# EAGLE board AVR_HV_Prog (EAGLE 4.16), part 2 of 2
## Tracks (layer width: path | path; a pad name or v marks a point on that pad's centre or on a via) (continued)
PAGEL  (via drill 0.5 pad 1.27, 0.6 pad 1.27) (continued)
  Top 0.406: 56.2,57.17 55.79,58.27 | 55.79,58.27 v56.2,58.42 | 56.2,57.17 56.6,58.27 | v56.2,58.42 56.6,58.27 | 56.2,57.17 55.79,58.27 | v56.2,58.42 55.79,58.27 | 55.78,40.13 56.2,41.51 | 55.78,40.13 | 56.2,41.51 | 55.78,40.13 56.2,41.51 | 55.78,40.13 | v56.2,40.01 55.78,40.13 | 56.61,40.13 56.2,41.51 | 55.78,40.13 56.2,41.51 | v56.2,40.01 55.78,40.13 | 56.61,40.13 56.2,41.51 | 56.61,40.13 | v56.2,40.01 56.61,40.13 | 55.78,40.13 56.2,41.51 | v56.2,40.01 55.78,40.13 | 56.61,40.13 56.2,41.51 | v56.2,40.01 56.61,40.13
  Top 0.61: 56.2,59.67 | 56.2,59.67 56.2,69.87 | 56.2,69.87 | 56.2,41.51 | 56.2,41.51 56.2,57.17 | 56.2,57.17
  Bottom 0.61: IC6.2 79.38,57.15 78.11,58.42 57.45,58.42 | v56.2,71.12 54.95,71.12 | 54.95,71.12 IC4.13 | v56.2,58.42 57.45,58.42 | 46.35,30.16 46.35,28.89 45.4,27.94 45.4,24.77 46.04,24.13 47.62,24.13 49.53,22.23 IC3.17 49.53,20.95 50.48,20 50.48,14.29 49.85,13.65 48.26,13.65 46.99,12.38 IC2.21 | 46.35,30.16 46.99,30.8 50.8,30.8 52.7,32.7 53.34,32.7 56.2,35.56 56.2,38.51 | 56.2,38.51 v56.2,40.01 | R18.2 40.96,30.8 45.72,30.8 46.35,30.16 | 54.95,71.12 56.11,70.8 v56.2,71.12 | 54.95,71.12 56.11,71.44 v56.2,71.12 | 57.45,58.42 56.28,58.74 v56.2,58.42 | 57.45,58.42 56.28,58.1 v56.2,58.42 | 56.2,38.51 56.52,39.93 v56.2,40.01 | 56.2,38.51 55.88,39.93 v56.2,40.01
R/B  (via drill 0.5 pad 1.27, 0.6 pad 1.27)
  Top 0.406: v68.9,52.39 68.9,53.64 | 68.9,59.71 v68.9,60.96 | v70.17,44.77 71.67,44.77 | 74.7,44.77 v76.2,44.77 | 49.76,15.56 v48.26,15.56 | v58.42,15.56 56.92,15.56 | 68.9,59.71 69.34,60.77 v68.9,60.96 | 68.9,59.71 68.45,60.77 v68.9,60.96 | 68.9,59.71 69.34,60.77 | 68.9,59.71 68.45,60.77 | 68.9,59.71 69.34,60.77 | v68.9,60.96 69.34,60.77 | 68.9,59.71 68.45,60.77 | v68.9,60.96 68.45,60.77 | 68.9,53.64 68.45,52.57 | v68.9,52.39 68.45,52.57 | 68.9,53.64 69.34,52.57 | v68.9,52.39 69.34,52.57 | 68.45,52.57 68.9,53.64 | 69.34,52.57 68.9,53.64 | 68.9,53.64 68.45,52.57 | v68.9,52.39 68.45,52.57 | 68.9,53.64 69.34,52.57 | v68.9,52.39 69.34,52.57 | 74.7,44.77 76.05,44.31 | v76.2,44.77 76.05,44.31 | 74.7,44.77 76.05,45.22 | v76.2,44.77 76.05,45.22 | 74.7,44.77 76.05,44.31 | 74.7,44.77 76.05,45.22 | 74.7,44.77 76.05,44.31 | v76.2,44.77 76.05,44.31 | 74.7,44.77 76.05,45.22 | v76.2,44.77 76.05,45.22 | 71.67,44.77 70.32,45.22 | v70.17,44.77 70.32,45.22 | 71.67,44.77 70.32,44.31 | v70.17,44.77 70.32,44.31 | 71.67,44.77 70.32,45.22 | 71.67,44.77 70.32,44.31 | 70.32,45.22 71.67,44.77 | v70.17,44.77 70.32,45.22 | 70.32,44.31 71.67,44.77 | v70.17,44.77 70.32,44.31 | 49.76,15.56 48.41,16.01 | v48.26,15.56 48.41,16.01 | 49.76,15.56 48.41,15.1 | v48.26,15.56 48.41,15.1 | 49.76,15.56 48.41,16.01 | 49.76,15.56 48.41,15.1 | 49.76,15.56 48.41,16.01 | v48.26,15.56 48.41,16.01 | 49.76,15.56 48.41,15.1 | v48.26,15.56 48.41,15.1 | 56.92,15.56 58.27,15.1 | v58.42,15.56 58.27,15.1 | 56.92,15.56 58.27,16.01 | v58.42,15.56 58.27,16.01 | 58.27,15.1 56.92,15.56 | 58.27,16.01 56.92,15.56 | 56.92,15.56 58.27,15.1 | v58.42,15.56 58.27,15.1 | 56.92,15.56 58.27,16.01 | v58.42,15.56 58.27,16.01 | 69.3,60.81 68.9,59.71
  Top 0.406: 68.9,59.71 | 68.49,60.81 68.9,59.71 | 68.9,59.71 69.3,60.81 | 69.3,60.81 v68.9,60.96 | 68.9,59.71 68.49,60.81 | 68.49,60.81 v68.9,60.96 | 68.9,59.71 69.3,60.81 | v68.9,60.96 69.3,60.81 | 68.9,59.71 68.49,60.81 | v68.9,60.96 68.49,60.81 | 68.9,53.64 | 68.49,52.54 68.9,53.64 | 68.49,52.54 | v68.9,52.39 68.49,52.54 | 69.3,52.54 68.9,53.64 | 69.3,52.54 | v68.9,52.39 69.3,52.54 | 68.49,52.54 68.9,53.64 | 69.3,52.54 68.9,53.64 | 68.49,52.54 68.9,53.64 | v68.9,52.39 68.49,52.54 | 69.3,52.54 68.9,53.64 | v68.9,52.39 69.3,52.54 | 76.08,44.35 74.7,44.77 | 76.08,44.35 | 74.7,44.77 | 74.7,44.77 76.08,44.35 | 76.08,44.35 | v76.2,44.77 76.08,44.35 | 76.08,45.18 74.7,44.77 | 74.7,44.77 76.08,44.35 | 76.08,44.35 v76.2,44.77 | 74.7,44.77 76.08,45.18 | 76.08,45.18 | 76.08,45.18 v76.2,44.77 | 74.7,44.77 76.08,44.35 | v76.2,44.77 76.08,44.35 | 76.08,45.18 74.7,44.77 | 76.08,45.18 v76.2,44.77 | 70.29,45.18 71.67,44.77 | 70.29,45.18 | 70.29,45.18 71.67,44.77 | v70.17,44.77 70.29,45.18 | 71.67,44.77 | 70.29,44.35 71.67,44.77 | 70.29,44.35 | v70.17,44.77 70.29,44.35 | 70.29,45.18 71.67,44.77 | 70.29,44.35 71.67,44.77 | v70.17,44.77 70.29,44.35 | 70.29,45.18 71.67,44.77 | v70.17,44.77 70.29,45.18 | 70.29,44.35 71.67,44.77 | v70.17,44.77 70.29,44.35 | 49.76,15.56 48.38,15.97 | 48.38,15.97 | 48.38,15.97 49.76,15.56 | 48.38,15.97 v48.26,15.56 | 49.76,15.56 | 48.38,15.14 49.76,15.56 | 48.38,15.14 | 48.38,15.14 v48.26,15.56 | 49.76,15.56 48.38,15.97 | 49.76,15.56 48.38,15.14 | 48.38,15.14 v48.26,15.56 | 48.38,15.97 49.76,15.56 | 48.38,15.97 v48.26,15.56 | 49.76,15.56 48.38,15.14 | v48.26,15.56 48.38,15.14 | 58.3,15.14 56.92,15.56 | 58.3,15.14 | 56.92,15.56 | 58.3,15.14 56.92,15.56 | 58.3,15.14 | v58.42,15.56 58.3,15.14 | 58.3,15.97 56.92,15.56
  Top 0.406: 58.3,15.14 56.92,15.56 | v58.42,15.56 58.3,15.14 | 58.3,15.97 56.92,15.56 | 58.3,15.97 v58.42,15.56 | 58.3,15.14 56.92,15.56 | v58.42,15.56 58.3,15.14 | 58.3,15.97 56.92,15.56 | v58.42,15.56 58.3,15.97
  Top 0.61: 68.9,53.64 | 68.9,53.64 68.9,59.71 | 68.9,59.71 | 71.67,44.77 | 71.67,44.77 74.7,44.77 | 74.7,44.77 | 56.92,15.56 | 56.92,15.56 49.76,15.56 | 49.76,15.56
  Bottom 0.61: IC6.3 79.38,59.69 78.11,60.96 70.15,60.96 | v76.2,44.77 76.2,43.27 | 76.2,43.27 IC5.9 | v68.9,60.96 70.15,60.96 | v70.17,44.77 70.8,44.77 71.44,45.4 71.44,45.57 | v70.17,44.77 68.67,44.77 | 68.67,44.77 67.63,44.77 66.67,43.81 66.67,42.23 65.41,40.96 65.41,35.24 59.69,29.53 IC2.15 59.69,26.35 61.91,24.13 62.87,24.13 64.77,22.23 IC3.11 64.77,20.64 62.23,18.1 62.23,14.92 | 68.01,51.5 62.23,45.72 IC4.3 51.44,45.72 49.85,44.13 49.85,39.05 50.8,38.1 50.8,33.97 49.53,32.7 33.02,32.7 | 68.01,51.5 v68.9,52.39 | 71.44,45.57 71.44,47.62 73.34,49.53 73.34,51.12 72.07,52.39 70.15,52.39 | v68.9,52.39 70.15,52.39 | 33.02,32.7 27.3,32.7 26.99,32.38 17.14,32.38 R13.2 | 33.02,32.7 JP1.1 | 62.23,14.92 63.5,13.65 IC7.9 | IC8.7 40.64,15.88 42.23,14.29 46.35,14.29 46.99,14.92 47.08,14.92 | v48.26,15.56 47.08,14.92 | v58.42,15.56 58.42,15.24 59.31,14.67 | 59.31,14.67 59.69,14.29 61.59,14.29 62.23,14.92 | 70.15,60.96 68.98,61.28 v68.9,60.96 | 70.15,60.96 68.98,60.64 v68.9,60.96 | 68.01,51.5 69.06,52.1 v68.9,52.39 | 68.01,51.5 68.61,52.55 v68.9,52.39 | 70.15,52.39 68.98,52.71 v68.9,52.39 | 70.15,52.39 68.98,52.07 v68.9,52.39 | 76.2,43.27 76.52,44.7 v76.2,44.77 | 76.2,43.27 75.88,44.7 v76.2,44.77 | 68.67,44.77 70.09,44.45 v70.17,44.77 | 68.67,44.77 70.09,45.09 v70.17,44.77 | 71.44,45.57 70.06,45.08 v70.17,44.77 | 71.44,45.57 70.4,44.53 v70.17,44.77 | 47.08,14.92 48.19,15.23 v48.26,15.56 | 47.08,14.92 48.19,15.88 v48.26,15.56 | 59.31,14.67 58.72,15.69 v58.42,15.56 | 59.31,14.67 58.2,15.31 v58.42,15.56
U_IN
  Bottom 0.61: X2.+ 8.26,13.97 8.26,12.38 9.21,11.43 IC10.IN 13.02,5.71 13.84,4.89 C4.+
VCC  (via drill 0.6 pad 1.27)
  Top 0.406: v31.75,54.61 31.75,56.11 | 31.75,72.16 31.74,72.19 | 31.74,72.19 v31.43,73.66 | v18.1,26.04 17.78,27.54 | 17.78,42.95 v17.78,44.45 | 31.75,72.16 31.89,73.5 v31.43,73.66 | 31.73,72.19 30.98,73.5 | 30.98,73.5 v31.43,73.66 | 31.75,72.16 31.75,72.19 | 31.75,72.16 31.73,72.19 | 31.75,72.19 31.89,73.19 v31.43,73.66 | 31.75,72.19 31.75,72.16 | 31.73,72.19 30.98,73.5 | 31.73,72.19 | 31.73,72.19 31.75,72.16 | 30.98,73.5 v31.43,73.66 | 31.75,56.11 31.29,54.77 | v31.75,54.61 31.29,54.77 | 31.75,56.11 32.21,54.77 | v31.75,54.61 32.21,54.77 | 31.29,54.77 31.75,56.11 | 32.21,54.77 31.75,56.11 | 31.75,56.11 31.29,54.77 | v31.75,54.61 31.29,54.77 | 31.75,56.11 32.21,54.77 | v31.75,54.61 32.21,54.77 | 17.78,42.95 18.24,44.3 | v17.78,44.45 18.24,44.3 | 17.78,42.95 17.32,44.3 | v17.78,44.45 17.32,44.3 | 17.78,42.95 18.24,44.3 | 17.78,42.95 17.32,44.3 | 17.78,42.95 18.24,44.3 | v17.78,44.45 18.24,44.3 | 17.78,42.95 17.32,44.3 | v17.78,44.45 17.32,44.3 | 17.64,26.19 17.78,27.5 | v18.1,26.04 17.64,26.19 | 17.78,28.89 17.78,33.02 | 17.78,39.69 17.78,42.95 | 17.78,42.95 | 18.55,26.19 17.8,27.5 | v18.1,26.04 18.55,26.19 | 17.64,26.19 17.78,27.5 | 17.78,27.5 17.78,27.54 | 17.8,27.5 17.78,27.54 | 17.78,27.54 17.78,27.5 | 17.64,26.19 17.78,27.5 | v18.1,26.04 17.64,26.19 | 17.78,27.54 17.8,27.5 | 18.55,26.19 17.8,27.5 | v18.1,26.04 18.55,26.19 | 31.74,72.19 31.86,73.62 | 31.86,73.62 v31.43,73.66 | 31.74,72.19 31.05,73.45 | 31.05,73.45 v31.43,73.66 | 31.86,73.62 31.75,72.19 31.05,73.45 | 31.86,73.63 31.86,73.62 | v31.43,73.66 31.86,73.63 | v31.43,73.66 31.05,73.45 | 31.75,72.19 31.86,73.62 | 31.86,73.62 31.86,73.63 | 31.75,72.19 31.05,73.45 | 31.73,72.19 31.86,73.62 | 31.86,73.62 | v31.43,73.66 31.86,73.62
  Top 0.406: 31.73,72.19 31.05,73.45 | 31.05,73.45 | 31.86,73.62 31.75,72.19 | 31.86,73.62 31.86,73.63 | v31.43,73.66 31.86,73.63 | 31.05,73.45 31.75,72.19 | 31.05,73.45 v31.43,73.66 | 31.73,72.19 31.86,73.62 | 31.86,73.62 v31.43,73.66 | 31.73,72.19 31.05,73.45 | v31.43,73.66 31.05,73.45 | 31.34,54.73 31.75,56.11 | 31.34,54.73 | 31.34,54.73 | v31.75,54.61 31.34,54.73 | 31.34,54.73 31.75,56.11 | v31.75,54.61 31.34,54.73 | 32.16,54.73 31.75,56.11 | 32.16,54.73 | v31.75,54.61 32.16,54.73 | 31.34,54.73 31.75,56.11 | v31.75,54.61 31.34,54.73 | 31.75,56.11 | 32.16,54.73 31.75,56.11 | v31.75,54.61 32.16,54.73 | 17.78,42.95 18.19,44.33 | 18.19,44.33 | 18.19,44.33 17.78,42.95 | 18.19,44.33 v17.78,44.45 | 17.78,42.95 | 17.37,44.33 17.78,42.95 | 17.37,44.33 | 17.37,44.33 v17.78,44.45 | 17.78,42.95 18.19,44.33 | 17.78,42.95 17.37,44.33 | 17.37,44.33 v17.78,44.45 | 18.19,44.33 17.78,42.95 | 18.19,44.33 v17.78,44.45 | 17.78,42.95 17.37,44.33 | v17.78,44.45 17.37,44.33 | 17.67,26.07 17.79,27.5 18.48,26.25 | 17.67,26.07 v18.1,26.04 | 18.48,26.25 18.48,26.24 v18.1,26.04 | 18.48,26.25 | 18.48,26.25 17.8,27.5 | 18.48,26.25 18.48,26.24 | 17.67,26.07 17.78,27.5 | 18.48,26.25 17.78,27.5 | v18.1,26.04 18.48,26.25 | 17.67,26.07 17.8,27.5 | 18.48,26.24 17.8,27.5 | 17.67,26.07 17.78,27.5 | 17.67,26.07 v18.1,26.04 | 18.48,26.25 17.78,27.5 | v18.1,26.04 18.48,26.25 | 17.67,26.07 17.8,27.5 | v18.1,26.04 17.67,26.07 | 18.48,26.24 17.8,27.5 | v18.1,26.04 18.48,26.24
  Top 0.61: 31.75,56.11 | 31.75,56.11 31.75,72.16 | 17.78,27.54 17.78,28.89 | 17.78,33.02 17.78,39.69
  Bottom 0.61: Q5.1 R10.2 31.96,53.12 | IC11.6 20.95,17.78 19.68,19.05 R14.1 18.1,19.05 15.43,21.72 15.43,21.78 | v31.43,73.66 29.93,73.66 | 29.93,73.66 IC1.9 | v31.75,54.61 31.75,53.34 | 31.75,53.34 31.96,53.12 | 31.43,56.11 31.43,56.52 30.8,57.15 26.67,57.15 22.86,53.34 IC1.20 C5.1 18.1,46.67 18.1,45.92 | 31.43,56.11 v31.75,54.61 | 31.75,53.34 30.95,53.34 | 30.95,53.34 IC1.1 | 15.43,21.78 C2.+ 15.43,24.64 16.19,25.4 16.74,25.4 | 15.43,21.78 13.02,19.37 IC10.OUT | 18.1,45.92 18.1,44.77 v17.78,44.45 | 16.74,25.4 17.46,25.4 v18.1,26.04 | 29.93,73.66 31.36,73.34 v31.43,73.66 | 29.93,73.66 31.36,73.98 v31.43,73.66 | 31.96,53.12 32.08,54.58 v31.75,54.61 | 31.96,53.12 31.44,54.49 v31.75,54.61 | 31.43,56.11 31.43,54.68 v31.75,54.61 | 31.43,56.11 32.07,54.68 v31.75,54.61 | 30.95,53.34 31.98,54.38 v31.75,54.61 | 30.95,53.34 31.44,54.72 v31.75,54.61 | 18.1,45.92 17.48,44.59 v17.78,44.45 | 18.1,45.92 18.11,44.45 v17.78,44.45 | 16.74,25.4 18.17,25.71 v18.1,26.04 | 16.74,25.4 17.89,26.3 v18.1,26.04
VCC_P  (via drill 0.6 pad 1.27)
  Top 0.406: v70.48,30.48 71.98,30.48 | 82.32,30.48 v83.82,30.48 | v41.91,59.69 41.91,61.19 | 41.91,74.7 v41.91,76.2 | v41.91,49.53 41.91,51.03 | 41.91,58.19 v41.91,59.69 | v40.64,13.65 42.14,13.65 | 64.22,13.65 64.54,13.65 | 64.54,13.65 v66.04,13.65 | 82.32,30.48 83.67,30.02 | v83.82,30.48 83.67,30.02 | 82.32,30.48 83.67,30.94 | v83.82,30.48 83.67,30.94 | 82.32,30.48 83.67,30.02 | 82.32,30.48 83.67,30.94 | 82.32,30.48 83.67,30.02 | v83.82,30.48 83.67,30.02 | 82.32,30.48 83.67,30.94 | v83.82,30.48 83.67,30.94 | 71.98,30.48 70.64,30.94 | v70.48,30.48 70.64,30.94 | 71.98,30.48 | 82.32,30.48 | 71.98,30.48 70.64,30.02 | v70.48,30.48 70.64,30.02 | 71.98,30.48 70.64,30.94 | 71.98,30.48 70.64,30.02 | 70.64,30.94 71.98,30.48 | v70.48,30.48 70.64,30.94 | 70.64,30.02 71.98,30.48 | v70.48,30.48 70.64,30.02 | 41.91,74.7 42.37,76.05 | v41.91,76.2 42.37,76.05 | 41.91,74.7 41.45,76.05 | v41.91,76.2 41.45,76.05 | 41.91,74.7 42.37,76.05 | 41.91,74.7 41.45,76.05 | 41.91,74.7 42.37,76.05 | v41.91,76.2 42.37,76.05 | 41.91,74.7 41.45,76.05 | v41.91,76.2 41.45,76.05 | 41.91,61.19 41.45,59.84 | v41.91,59.69 41.45,59.84 | 41.91,61.19 42.37,59.84 | v41.91,59.69 42.37,59.84 | 41.91,58.19 42.37,59.53 | v41.91,59.69 42.37,59.53 | 41.91,58.19 41.45,59.53 | v41.91,59.69 41.45,59.53 | 41.45,59.84 41.91,61.19 | 42.37,59.84 41.91,61.19 | 41.91,61.19 41.45,59.84 | v41.91,59.69 41.45,59.84 | 41.91,61.19 42.37,59.84 | v41.91,59.69 42.37,59.84 | 41.91,58.19 42.37,59.53 | 41.91,58.19 41.45,59.53 | 41.91,58.19 42.37,59.53 | v41.91,59.69 42.37,59.53 | 41.91,58.19 41.45,59.53 | v41.91,59.69 41.45,59.53 | 41.91,51.03 41.45,49.69 | v41.91,49.53 41.45,49.69 | 41.91,51.03 42.37,49.69 | v41.91,49.53 42.37,49.69 | 41.45,49.69 41.91,51.03
  Top 0.406: 42.37,49.69 41.91,51.03 | 41.91,51.03 41.45,49.69 | v41.91,49.53 41.45,49.69 | 41.91,51.03 42.37,49.69 | v41.91,49.53 42.37,49.69 | 42.14,13.65 40.8,14.11 | v40.64,13.65 40.8,14.11 | 42.14,13.65 40.8,13.2 | v40.64,13.65 40.8,13.2 | 42.14,13.65 40.8,14.11 | 42.14,13.65 40.8,13.2 | 40.8,14.11 42.14,13.65 | v40.64,13.65 40.8,14.11 | 40.8,13.2 42.14,13.65 | v40.64,13.65 40.8,13.2 | 64.54,13.56 65.89,13.2 | v66.04,13.65 65.89,13.2 | 64.22,13.65 65.89,14.11 | 65.89,14.11 v66.04,13.65 | 65.89,13.2 64.54,13.56 | 64.54,13.56 64.22,13.65 | 65.89,14.11 64.54,13.74 | 64.54,13.74 64.22,13.65 | 64.22,13.65 64.54,13.56 | 64.54,13.56 65.89,13.2 | v66.04,13.65 65.89,13.2 | 64.22,13.65 65.89,14.11 | 65.89,14.11 v66.04,13.65 | 83.69,30.07 82.32,30.48 | 83.69,30.07 83.7,30.07 | 82.32,30.48 | 82.32,30.48 83.7,30.07 | 83.7,30.07 | v83.82,30.48 83.7,30.07 | 83.69,30.89 82.32,30.48 | 82.32,30.48 83.69,30.07 | 83.69,30.07 v83.82,30.48 | 82.32,30.48 83.69,30.89 | 83.69,30.89 83.7,30.89 v83.82,30.48 | 82.32,30.48 83.7,30.07 | v83.82,30.48 83.7,30.07 | 83.69,30.89 82.32,30.48 | 83.69,30.89 v83.82,30.48 | 70.61,30.89 71.98,30.48 | 70.61,30.89 | 70.61,30.89 71.98,30.48 | v70.48,30.48 70.61,30.89 | 71.98,30.48 | 70.61,30.07 71.98,30.48 | 70.61,30.07 | v70.48,30.48 70.61,30.07 | 70.61,30.89 71.98,30.48 | 70.61,30.07 71.98,30.48 | v70.48,30.48 70.61,30.07 | 70.61,30.89 71.98,30.48 | v70.48,30.48 70.61,30.89 | 70.61,30.07 71.98,30.48 | v70.48,30.48 70.61,30.07 | 41.91,74.7 42.32,76.08 | 42.32,76.08 | 42.32,76.08 41.91,74.7 | 42.32,76.08 v41.91,76.2 | 41.91,74.7 | 41.5,76.08 41.91,74.7 | 41.5,76.08 | 41.5,76.08 v41.91,76.2 | 41.91,74.7 42.32,76.08 | 41.91,74.7 41.5,76.08 | 41.5,76.08 v41.91,76.2 | 42.32,76.08 41.91,74.7
  Top 0.406: 42.32,76.08 v41.91,76.2 | 41.91,74.7 41.5,76.08 | v41.91,76.2 41.5,76.08 | 41.5,59.81 41.91,61.19 | 41.5,59.81 | 41.91,61.19 | 41.91,58.19 42.32,59.57 | 42.32,59.57 | 41.5,59.81 41.91,61.19 | 41.5,59.81 | v41.91,59.69 41.5,59.81 | 42.32,59.81 41.91,61.19 | 41.5,59.81 41.91,61.19 | v41.91,59.69 41.5,59.81 | 42.32,59.81 41.91,61.19 | 42.32,59.81 | v41.91,59.69 42.32,59.81 | 41.5,59.81 41.91,61.19 | v41.91,59.69 41.5,59.81 | 42.32,59.81 41.91,61.19 | v41.91,59.69 42.32,59.81 | 42.32,59.57 41.91,58.19 | 42.32,59.57 v41.91,59.69 | 41.91,58.19 | 41.5,59.57 41.91,58.19 | 41.5,59.57 | 41.5,59.57 v41.91,59.69 | 41.91,58.19 42.32,59.57 | 41.91,58.19 41.5,59.57 | 41.5,59.57 v41.91,59.69 | 42.32,59.57 41.91,58.19 | 42.32,59.57 v41.91,59.69 | 41.91,58.19 41.5,59.57 | v41.91,59.69 41.5,59.57 | 41.5,49.65 41.91,51.03 | 41.5,49.65 | 41.91,51.03 | 41.5,49.65 41.91,51.03 | 41.5,49.65 | v41.91,49.53 41.5,49.65 | 42.32,49.65 41.91,51.03 | 41.5,49.65 41.91,51.03 | v41.91,49.53 41.5,49.65 | 42.32,49.65 41.91,51.03 | 42.32,49.65 | v41.91,49.53 42.32,49.65 | 41.5,49.65 41.91,51.03 | v41.91,49.53 41.5,49.65 | 42.32,49.65 41.91,51.03 | v41.91,49.53 42.32,49.65 | 40.76,14.07 42.14,13.65 | 40.76,14.07 | 40.76,14.07 42.14,13.65 | v40.64,13.65 40.76,14.07 | 42.14,13.65 | 40.76,13.24 42.14,13.65 | 40.76,13.24 | v40.64,13.65 40.76,13.24 | 40.76,14.07 42.14,13.65 | 40.76,13.24 42.14,13.65 | v40.64,13.65 40.76,13.24 | 40.76,14.07 42.14,13.65 | v40.64,13.65 40.76,14.07 | 40.76,13.24 42.14,13.65 | v40.64,13.65 40.76,13.24 | 64.54,13.65 65.92,13.24 v66.04,13.65 | 64.54,13.65 65.92,14.07 v66.04,13.65 | 65.94,14.07 | 65.94,13.23 64.54,13.56 | 65.94,13.23 | v66.04,13.65 65.94,13.23 | 65.89,14.06 64.54,13.56 | 65.89,13.25 64.54,13.74
  Top 0.406: 65.89,13.25 v66.04,13.65 | 65.94,14.07 64.54,13.74 | v66.04,13.65 65.94,14.07 | 64.54,13.56 65.94,13.23 | v66.04,13.65 65.94,13.23 | 64.54,13.56 65.89,14.06 | v66.04,13.65 65.89,14.06 | 64.54,13.74 65.89,13.25 | v66.04,13.65 65.89,13.25 | 64.54,13.74 65.94,14.07 | v66.04,13.65 65.94,14.07
  Top 0.61: 71.98,30.48 82.32,30.48 | 41.91,61.19 | 41.91,61.19 41.91,74.7 | 41.91,74.7 | 41.91,51.03 | 41.91,51.03 41.91,58.19 | 41.91,58.19 | 42.14,13.65 | 42.14,13.65 64.22,13.65
  Bottom 0.61: IC5.5 86.36,37.78 83.82,35.24 IC5.15 83.82,31.98 | v83.82,30.48 83.82,31.98 | v41.91,76.2 41.27,76.2 40.58,75.5 | 40.58,75.5 40.01,74.93 RN1.1 38.73,74.93 37.47,76.2 C6.1 | v41.91,59.69 42.23,59.69 43.12,60.58 | 43.12,60.58 43.5,60.96 IC4.20 | v70.48,30.48 70.48,31.98 | 70.48,31.98 70.48,34.92 69.85,35.56 69.85,37.78 72.39,40.32 72.39,42.23 73.66,43.5 73.66,46.67 75.56,48.58 75.56,54.61 IC6.20 74.61,54.61 73.34,55.88 IC4.7 49.85,55.88 47.62,53.66 47.62,51.44 45.72,49.53 43.41,49.53 | v70.48,30.48 70.48,29.53 70.96,29.06 | 70.96,29.06 72.39,27.62 IC2.10 72.39,26.04 70.48,24.13 69.85,24.13 68.58,22.86 68.58,20.32 67.31,19.05 67.31,14.92 | IC3.40 90.17,7.3 88.9,8.57 88.9,12.7 87.95,13.65 77.47,13.65 76.2,14.92 | 43.41,49.53 v41.91,49.53 | R11.1 36.51,45.72 39.05,48.26 Q5.3 39.37,48.58 40.32,49.53 40.41,49.53 | v41.91,49.53 40.41,49.53 | 67.31,14.92 69.85,12.38 | 69.85,12.38 IC2.30 | 69.85,12.38 71.91,14.45 75.72,14.45 76.2,14.92 | 76.2,14.92 IC7.1 | 39.58,13.76 v40.64,13.65 | v66.04,13.65 67.1,14.71 | 67.1,14.71 67.31,14.92 | 83.82,31.98 83.5,30.55 v83.82,30.48 | 83.82,31.98 84.14,30.55 v83.82,30.48 | 70.48,31.98 70.16,30.55 v70.48,30.48 | 70.48,31.98 70.81,30.55 v70.48,30.48 | 70.96,29.06 70.81,30.51 v70.48,30.48 | 70.96,29.06 70.2,30.31 v70.48,30.48 | 40.58,75.5 41.99,75.88 v41.91,76.2 | 40.58,75.5 41.7,76.45 v41.91,76.2 | 43.12,60.58 41.78,59.99 v41.91,59.69 | 43.12,60.58 42.16,59.47 v41.91,59.69 | 43.41,49.53 41.98,49.85 v41.91,49.53 | 43.41,49.53 41.98,49.21 v41.91,49.53 | 40.41,49.53 41.84,49.21 v41.91,49.53 | 40.41,49.53 41.84,49.85 v41.91,49.53 | 39.58,13.76 40.36,13.48 v40.64,13.65
  Bottom 0.61: 39.58,13.76 40.82,13.93 v40.64,13.65 | 67.1,14.71 65.86,13.93 v66.04,13.65 | 67.1,14.71 66.32,13.48 v66.04,13.65 | IC8.8 38.1,15.24 39.58,13.76
XA0  (via drill 0.5 pad 1.27, 0.6 pad 1.27)
  Top 0.406: v59.37,66.04 59.37,67.29 | 59.37,74.95 v59.37,76.2 | v85.09,74.93 85.09,73.68 | 85.09,73.64 v85.09,72.39 | v59.37,40.01 59.37,41.51 | 59.37,64.79 v59.37,66.04 | 59.37,67.29 58.93,66.23 | v59.37,66.04 58.93,66.23 | 59.37,67.29 59.82,66.23 | v59.37,66.04 59.82,66.23 | 59.37,64.79 59.82,65.85 v59.37,66.04 | 59.37,64.79 58.93,65.85 v59.37,66.04 | 58.93,66.23 59.37,67.29 | 59.82,66.23 59.37,67.29 | 59.37,67.29 58.93,66.23 | v59.37,66.04 58.93,66.23 | 59.37,67.29 59.82,66.23 | v59.37,66.04 59.82,66.23 | 59.37,64.79 59.82,65.85 | 59.37,64.79 58.93,65.85 | 59.37,64.79 59.82,65.85 | v59.37,66.04 59.82,65.85 | 59.37,64.79 58.93,65.85 | v59.37,66.04 58.93,65.85 | 59.37,74.95 59.82,76.01 v59.37,76.2 | 59.37,74.95 58.93,76.01 v59.37,76.2 | 59.37,74.95 59.82,76.01 | 59.37,74.95 58.93,76.01 | 59.37,74.95 59.82,76.01 | v59.37,76.2 59.82,76.01 | 59.37,74.95 58.93,76.01 | v59.37,76.2 58.93,76.01 | 85.09,73.64 84.64,72.58 | v85.09,72.39 84.64,72.58 | 85.09,73.64 85.53,72.58 | v85.09,72.39 85.53,72.58 | 85.09,73.64 84.64,72.58 | 85.09,73.64 85.53,72.58 | 85.09,73.64 84.64,72.58 | v85.09,72.39 84.64,72.58 | 85.09,73.64 85.53,72.58 | v85.09,72.39 85.53,72.58 | 85.09,73.68 85.53,74.74 v85.09,74.93 | 85.09,73.68 84.64,74.74 v85.09,74.93 | 85.09,73.68 85.53,74.74 | 85.09,73.68 84.64,74.74 | 85.53,74.74 85.09,73.68 | v85.09,74.93 85.53,74.74 | 84.64,74.74 85.09,73.68 | v85.09,74.93 84.64,74.74 | 59.37,41.51 58.92,40.16 | v59.37,40.01 58.92,40.16 | 59.37,41.51 59.83,40.16 | v59.37,40.01 59.83,40.16 | 58.92,40.16 59.37,41.51 | 59.83,40.16 59.37,41.51 | 59.37,41.51 58.92,40.16 | v59.37,40.01 58.92,40.16 | 59.37,41.51 59.83,40.16 | v59.37,40.01 59.83,40.16 | 59.37,67.29 | 58.97,66.19 59.37,67.29
  Top 0.406: 58.97,66.19 | v59.37,66.04 58.97,66.19 | 59.78,66.19 59.37,67.29 | 59.78,66.19 | v59.37,66.04 59.78,66.19 | 58.97,66.19 59.37,67.29 | 59.78,66.19 59.37,67.29 | 58.97,66.19 59.37,67.29 | v59.37,66.04 58.97,66.19 | 59.78,66.19 59.37,67.29 | v59.37,66.04 59.78,66.19 | 59.78,65.89 59.37,64.79 | 59.37,64.79 | 58.97,65.89 59.37,64.79 | 59.37,64.79 59.78,65.89 | 59.78,65.89 v59.37,66.04 | 59.37,64.79 58.97,65.89 | 58.97,65.89 v59.37,66.04 | 59.37,64.79 59.78,65.89 | v59.37,66.04 59.78,65.89 | 59.37,64.79 58.97,65.89 | v59.37,66.04 58.97,65.89 | 59.78,76.05 59.37,74.95 | 59.37,74.95 | 58.97,76.05 59.37,74.95 | 59.37,74.95 59.78,76.05 | 59.78,76.05 v59.37,76.2 | 59.37,74.95 58.97,76.05 | 58.97,76.05 v59.37,76.2 | 59.37,74.95 59.78,76.05 | v59.37,76.2 59.78,76.05 | 59.37,74.95 58.97,76.05 | v59.37,76.2 58.97,76.05 | 85.09,73.64 | 84.69,72.54 85.09,73.64 | 84.69,72.54 | v85.09,72.39 84.69,72.54 | 85.5,72.54 85.09,73.64 | 85.5,72.54 | 85.5,72.54 v85.09,72.39 | 85.09,73.64 84.69,72.54 | 85.09,73.64 85.5,72.54 | 84.69,72.54 85.09,73.64 | 84.69,72.54 v85.09,72.39 | 85.5,72.54 85.09,73.64 | 85.5,72.54 v85.09,72.39 | 85.5,74.78 85.09,73.68 | 85.09,73.68 | 84.69,74.78 85.09,73.68 | 85.5,74.78 85.09,73.68 | v85.09,74.93 85.5,74.78 | 84.69,74.78 85.09,73.68 | v85.09,74.93 84.69,74.78 | 85.5,74.78 85.09,73.68 | v85.09,74.93 85.5,74.78 | 84.69,74.78 85.09,73.68 | v85.09,74.93 84.69,74.78 | 58.96,40.13 59.37,41.51 | 58.96,40.13 | 59.37,41.51 | 58.96,40.13 59.37,41.51 | 58.96,40.13 | v59.37,40.01 58.96,40.13 | 59.79,40.13 59.37,41.51 | 58.96,40.13 59.37,41.51 | v59.37,40.01 58.96,40.13 | 59.79,40.13 59.37,41.51 | 59.79,40.13 | v59.37,40.01 59.79,40.13 | 58.96,40.13 59.37,41.51 | v59.37,40.01 58.96,40.13 | 59.79,40.13 59.37,41.51
  Top 0.406: v59.37,40.01 59.79,40.13
  Top 0.61: 59.37,67.29 | 59.37,67.29 59.37,74.95 | 59.37,74.95 | 85.09,73.68 | 85.09,73.68 85.09,73.64 | 85.09,73.64 | 59.37,41.51 | 59.37,41.51 59.37,64.79 | 59.37,64.79
  Bottom 0.406: 38.1,77.47 35.56,77.47
  Bottom 0.61: IC6.9 80.01,74.93 | v59.37,66.04 58.12,66.04 | 58.12,66.04 IC4.11 | IC6.9 79.38,74.93 78.11,76.2 60.62,76.2 | v59.37,76.2 60.62,76.2 | IC5.2 93.98,61.91 88.27,67.63 88.27,71.44 87.31,72.39 86.34,72.39 | v85.09,72.39 86.34,72.39 | IC6.9 83.84,74.93 | 83.84,74.93 v85.09,74.93 | IC3.15 54.61,22.23 52.7,24.13 51.75,24.13 49.53,26.35 IC2.19 49.53,27.3 51.12,28.89 52.07,28.89 53.98,30.8 54.61,30.8 59.37,35.56 59.37,38.51 | 59.37,38.51 v59.37,40.01 | 38.1,77.47 46.04,77.47 48.58,74.93 57.78,74.93 58.34,75.49 | 58.34,75.49 59.05,76.2 v59.37,76.2 | R25.2 IC1.11 22.23,76.2 26.04,72.39 32.54,72.39 32.86,72.71 32.86,73.5 34.61,75.25 34.61,76.52 35.56,77.47 | 58.12,66.04 59.28,65.72 v59.37,66.04 | 58.12,66.04 59.28,66.36 v59.37,66.04 | 60.62,76.2 59.46,76.52 v59.37,76.2 | 60.62,76.2 59.46,75.88 v59.37,76.2 | 58.34,75.49 59.48,75.89 v59.37,76.2 | 58.34,75.49 59.12,76.41 v59.37,76.2 | 86.34,72.39 85.18,72.71 v85.09,72.39 | 86.34,72.39 85.18,72.07 v85.09,72.39 | 83.84,74.93 85,74.61 v85.09,74.93 | 83.84,74.93 85,75.25 v85.09,74.93 | 59.37,38.51 59.7,39.93 v59.37,40.01 | 59.37,38.51 59.05,39.93 v59.37,40.01
XA1  (via drill 0.5 pad 1.27, 0.6 pad 1.27)
  Top 0.406: v57.78,68.58 57.78,69.83 | 57.78,76.86 v57.78,78.11 | v71.44,50.16 72.94,50.16 | 89.94,50.16 v91.44,50.16 | v57.78,41.91 57.78,43.41 | 57.78,67.33 v57.78,68.58 | 57.78,69.83 57.34,68.77 | v57.78,68.58 57.34,68.77 | 57.78,69.83 58.23,68.77 | v57.78,68.58 58.23,68.77 | 57.78,67.33 58.23,68.39 | v57.78,68.58 58.23,68.39 | 57.78,67.33 57.34,68.39 | v57.78,68.58 57.34,68.39 | 57.34,68.77 57.78,69.83 | 58.23,68.77 57.78,69.83 | 57.78,69.83 57.34,68.77 | v57.78,68.58 57.34,68.77 | 57.78,69.83 58.23,68.77 | v57.78,68.58 58.23,68.77 | 57.78,67.33 58.23,68.39 | 57.78,67.33 57.34,68.39 | 57.78,67.33 58.23,68.39 | v57.78,68.58 58.23,68.39 | 57.78,67.33 57.34,68.39 | v57.78,68.58 57.34,68.39 | 57.78,76.86 58.23,78.24 v57.78,78.11 | 57.78,76.86 57.34,78.24 v57.78,78.11 | 57.78,76.86 58.23,77.92 | 57.78,76.86 57.34,77.92 | 57.78,76.86 58.23,77.92 | v57.78,78.11 58.23,77.92 | 57.78,76.86 57.34,77.92 | v57.78,78.11 57.34,77.92 | 89.94,50.16 91.28,49.71 | v91.44,50.16 91.28,49.71 | 89.94,50.16 91.28,50.62 | v91.44,50.16 91.28,50.62 | 89.94,50.16 91.28,49.71 | 89.94,50.16 91.28,50.62 | 89.94,50.16 91.28,49.71 | v91.44,50.16 91.28,49.71 | 89.94,50.16 91.28,50.62 | v91.44,50.16 91.28,50.62 | 72.94,50.16 71.59,50.62 | v71.44,50.16 71.59,50.62 | 72.94,50.16 71.59,49.71 | v71.44,50.16 71.59,49.71 | 72.94,50.16 71.59,50.62 | 72.94,50.16 71.59,49.71 | 71.59,50.62 72.94,50.16 | v71.44,50.16 71.59,50.62 | 71.59,49.71 72.94,50.16 | v71.44,50.16 71.59,49.71 | 57.78,43.41 57.33,42.06 | v57.78,41.91 57.33,42.06 | 57.78,43.41 58.24,42.06 | v57.78,41.91 58.24,42.06 | 57.33,42.06 57.78,43.41 | 58.24,42.06 57.78,43.41 | 57.78,43.41 57.33,42.06 | v57.78,41.91 57.33,42.06 | 57.78,43.41 58.24,42.06
  Top 0.406: v57.78,41.91 58.24,42.06 | 57.78,69.83 | 57.38,68.73 57.78,69.83 | 57.38,68.73 | v57.78,68.58 57.38,68.73 | 58.19,68.73 57.78,69.83 | 58.19,68.73 | v57.78,68.58 58.19,68.73 | 57.38,68.73 57.78,69.83 | 58.19,68.73 57.78,69.83 | 57.38,68.73 57.78,69.83 | v57.78,68.58 57.38,68.73 | 58.19,68.73 57.78,69.83 | v57.78,68.58 58.19,68.73 | 58.19,68.43 57.78,67.33 | 57.78,67.33 | 57.38,68.43 57.78,67.33 | 57.78,67.33 58.19,68.43 | 58.19,68.43 v57.78,68.58 | 57.78,67.33 57.38,68.43 | 57.38,68.43 v57.78,68.58 | 57.78,67.33 58.19,68.43 | v57.78,68.58 58.19,68.43 | 57.78,67.33 57.38,68.43 | v57.78,68.58 57.38,68.43 | 58.19,77.96 57.78,76.86 | 57.78,76.86 | 57.38,77.96 57.78,76.86 | 57.78,76.86 58.19,77.96 | 58.19,77.96 v57.78,78.11 | 57.78,76.86 57.38,77.96 | 57.38,77.96 v57.78,78.11 | 57.78,76.86 58.19,77.96 | v57.78,78.11 58.19,77.96 | 57.78,76.86 57.38,77.96 | v57.78,78.11 57.38,77.96 | 91.32,49.75 89.94,50.16 | 91.32,49.75 | 89.94,50.16 | 89.94,50.16 91.32,49.75 | 91.32,49.75 | v91.44,50.16 91.32,49.75 | 91.32,50.58 89.94,50.16 | 89.94,50.16 91.32,49.75 | 91.32,49.75 v91.44,50.16 | 89.94,50.16 91.32,50.58 | 91.32,50.58 | 91.32,50.58 v91.44,50.16 | 89.94,50.16 91.32,49.75 | v91.44,50.16 91.32,49.75 | 91.32,50.58 89.94,50.16 | 91.32,50.58 v91.44,50.16 | 71.56,50.58 72.94,50.16 | 71.56,50.58 | 71.56,50.58 72.94,50.16 | v71.44,50.16 71.56,50.58 | 72.94,50.16 | 71.56,49.75 72.94,50.16 | 71.56,49.75 | v71.44,50.16 71.56,49.75 | 71.56,50.58 72.94,50.16 | 71.56,49.75 72.94,50.16 | v71.44,50.16 71.56,49.75 | 71.56,50.58 72.94,50.16 | v71.44,50.16 71.56,50.58 | 71.56,49.75 72.94,50.16 | v71.44,50.16 71.56,49.75 | 57.37,42.03 57.78,43.41 | 57.37,42.03 | 57.78,43.41 | 57.37,42.03 57.78,43.41 | 57.37,42.03 | v57.78,41.91 57.37,42.03
  Top 0.406: 58.2,42.03 57.78,43.41 | 57.37,42.03 57.78,43.41 | v57.78,41.91 57.37,42.03 | 58.2,42.03 57.78,43.41 | 58.2,42.03 | v57.78,41.91 58.2,42.03 | 57.37,42.03 57.78,43.41 | v57.78,41.91 57.37,42.03 | 58.2,42.03 57.78,43.41 | v57.78,41.91 58.2,42.03
  Top 0.61: 57.78,69.83 | 57.78,69.83 57.78,76.86 | 57.78,76.86 | 72.94,50.16 | 72.94,50.16 89.94,50.16 | 89.94,50.16 | 57.78,43.41 | 57.78,43.41 57.78,67.33 | 57.78,67.33
  Bottom 0.406: 32.7,74.93 30.8,74.93
  Bottom 0.61: v57.78,68.58 56.53,68.58 | 56.53,68.58 IC4.12 | v57.78,78.11 59.03,78.11 | 59.03,78.11 60.33,78.11 60.96,77.47 IC6.11 | v91.44,50.16 91.44,48.66 | 91.44,48.66 IC5.3 | 69.94,50.16 68.26,50.16 62.87,44.77 60.64,44.77 58.85,42.97 | 69.94,50.16 v71.44,50.16 | v57.78,41.91 58.85,42.97 | 57.78,40.41 57.78,35.56 53.98,31.75 53.34,31.75 51.44,29.84 50.48,29.84 49.53,28.89 48.26,28.89 46.99,27.62 IC2.20 46.99,26.35 49.21,24.13 50.16,24.13 52.07,22.23 IC3.16 | 57.78,40.41 v57.78,41.91 | 30.8,74.93 26.04,74.93 23.18,77.79 15.56,77.79 14.92,77.15 R27.1 | 57.52,76.88 57.78,77.15 v57.78,78.11 | 57.52,76.88 56.83,76.2 48.9,76.2 46.67,78.42 34.92,78.42 33.66,77.15 33.66,75.88 32.7,74.93 | 56.53,68.58 57.7,68.26 v57.78,68.58 | 56.53,68.58 57.7,68.9 v57.78,68.58 | 59.03,78.11 57.87,78.42 v57.78,78.11 | 59.03,78.11 57.87,77.79 v57.78,78.11 | 57.52,76.88 58.08,77.95 v57.78,78.11 | 57.52,76.88 57.45,78.09 v57.78,78.11 | 91.44,48.66 91.76,50.09 v91.44,50.16 | 91.44,48.66 91.12,50.09 v91.44,50.16 | 69.94,50.16 71.36,49.84 v71.44,50.16 | 69.94,50.16 71.36,50.49 v71.44,50.16 | 58.85,42.97 57.61,42.19 v57.78,41.91 | 58.85,42.97 58.06,41.73 v57.78,41.91 | 57.78,40.41 58.11,41.84 v57.78,41.91 | 57.78,40.41 57.46,41.84 v57.78,41.91
XTAL1  (via drill 0.6 pad 1.27)
  Top 0.406: v44.45,29.21 45.95,29.21 | 63.27,29.21 v64.77,29.21 | v66.67,60.96 66.67,62.46 | 66.67,64.54 v66.67,66.04 | v68.58,43.18 70.08,43.18 | 79.78,43.18 v81.28,43.18 | v66.67,40.01 66.67,41.51 | 66.67,59.46 v66.67,60.96 | v66.04,19.05 67.54,19.05 | 63.27,29.21 64.61,28.75 | v64.77,29.21 64.61,28.75 | 63.27,29.21 64.61,29.67 | v64.77,29.21 64.61,29.67 | 63.27,29.21 64.61,28.75 | 63.27,29.21 64.61,29.67 | 63.27,29.21 64.61,28.75 | v64.77,29.21 64.61,28.75 | 63.27,29.21 64.61,29.67 | v64.77,29.21 64.61,29.67 | 45.95,29.21 44.6,29.67 | v44.45,29.21 44.6,29.67 | 45.95,29.21 44.6,28.75 | v44.45,29.21 44.6,28.75 | 45.95,29.21 44.6,29.67 | 45.95,29.21 44.6,28.75 | 44.6,29.67 45.95,29.21 | v44.45,29.21 44.6,29.67 | 44.6,28.75 45.95,29.21 | v44.45,29.21 44.6,28.75 | 66.67,64.54 67.13,65.89 | v66.67,66.04 67.13,65.89 | 66.67,64.54 66.22,65.89 | v66.67,66.04 66.22,65.89 | 66.67,64.54 67.13,65.89 | 66.67,64.54 66.22,65.89 | 66.67,64.54 67.13,65.89 | v66.67,66.04 67.13,65.89 | 66.67,64.54 66.22,65.89 | v66.67,66.04 66.22,65.89 | 66.67,62.46 66.22,61.12 | v66.67,60.96 66.22,61.12 | 66.67,62.46 67.13,61.12 | v66.67,60.96 67.13,61.12 | 66.67,59.46 67.13,60.8 | v66.67,60.96 67.13,60.8 | 66.67,59.46 66.22,60.8 | v66.67,60.96 66.22,60.8 | 66.22,61.12 66.67,62.46 | 67.13,61.12 66.67,62.46 | 66.67,62.46 66.22,61.12 | v66.67,60.96 66.22,61.12 | 66.67,62.46 67.13,61.12 | v66.67,60.96 67.13,61.12 | 66.67,59.46 67.13,60.8 | 66.67,59.46 66.22,60.8 | 66.67,59.46 67.13,60.8 | v66.67,60.96 67.13,60.8 | 66.67,59.46 66.22,60.8 | v66.67,60.96 66.22,60.8 | 70.08,43.18 68.73,43.64 | v68.58,43.18 68.73,43.64 | 70.08,43.18 68.73,42.72 | v68.58,43.18 68.73,42.72 | 70.08,43.18 68.73,43.64 | 70.08,43.18 68.73,42.72
  Top 0.406: 68.73,43.64 70.08,43.18 | v68.58,43.18 68.73,43.64 | 68.73,42.72 70.08,43.18 | v68.58,43.18 68.73,42.72 | 79.78,43.18 81.12,42.72 | v81.28,43.18 81.12,42.72 | 79.78,43.18 81.12,43.64 | v81.28,43.18 81.12,43.64 | 79.78,43.18 81.12,42.72 | 79.78,43.18 81.12,43.64 | 79.78,43.18 81.12,42.72 | v81.28,43.18 81.12,42.72 | 79.78,43.18 81.12,43.64 | v81.28,43.18 81.12,43.64 | 66.67,41.51 66.22,40.16 | v66.67,40.01 66.22,40.16 | 66.67,41.51 67.13,40.16 | v66.67,40.01 67.13,40.16 | 66.22,40.16 66.67,41.51 | 67.13,40.16 66.67,41.51 | 66.67,41.51 66.22,40.16 | v66.67,40.01 66.22,40.16 | 66.67,41.51 67.13,40.16 | v66.67,40.01 67.13,40.16 | 67.54,19.05 66.19,19.51 | v66.04,19.05 66.19,19.51 | 67.54,19.05 66.19,18.59 | v66.04,19.05 66.19,18.59 | 67.54,19.05 66.19,19.51 | 67.54,19.05 66.19,18.59 | 66.19,19.51 67.54,19.05 | v66.04,19.05 66.19,19.51 | 66.19,18.59 67.54,19.05 | v66.04,19.05 66.19,18.59 | 72.16,19.05 73.5,18.59 | v73.66,19.05 73.5,18.59 | 72.16,19.05 73.5,19.51 | v73.66,19.05 73.5,19.51 | 72.16,19.05 73.5,18.59 | 72.16,19.05 73.5,19.51 | 72.16,19.05 73.5,18.59 | v73.66,19.05 73.5,18.59 | 72.16,19.05 73.5,19.51 | v73.66,19.05 73.5,19.51 | 64.64,28.8 63.27,29.21 | 64.64,28.8 64.65,28.8 | 63.27,29.21 | 63.27,29.21 64.65,28.8 | 64.65,28.8 | v64.77,29.21 64.65,28.8 | 64.64,29.62 63.27,29.21 | 63.27,29.21 64.64,28.8 | 64.64,28.8 v64.77,29.21 | 63.27,29.21 64.64,29.62 | 64.64,29.62 64.65,29.62 v64.77,29.21 | 63.27,29.21 64.65,28.8 | v64.77,29.21 64.65,28.8 | 64.64,29.62 63.27,29.21 | 64.64,29.62 v64.77,29.21 | 44.57,29.62 45.95,29.21 | 44.57,29.62 | 44.57,29.62 45.95,29.21 | v44.45,29.21 44.57,29.62 | 45.95,29.21 | 44.57,28.8 45.95,29.21 | 44.57,28.8 | v44.45,29.21 44.57,28.8 | 44.57,29.62 45.95,29.21
  Top 0.406: 44.57,28.8 45.95,29.21 | v44.45,29.21 44.57,28.8 | 44.57,29.62 45.95,29.21 | v44.45,29.21 44.57,29.62 | 44.57,28.8 45.95,29.21 | v44.45,29.21 44.57,28.8 | 66.67,64.54 67.09,65.92 | 67.09,65.92 | 67.09,65.92 66.67,64.54 | 67.09,65.92 v66.67,66.04 | 66.67,64.54 | 66.26,65.92 66.67,64.54 | 66.26,65.92 | 66.26,65.92 v66.67,66.04 | 66.67,64.54 67.09,65.92 | 66.67,64.54 66.26,65.92 | 66.26,65.92 v66.67,66.04 | 67.09,65.92 66.67,64.54 | 67.09,65.92 v66.67,66.04 | 66.67,64.54 66.26,65.92 | v66.67,66.04 66.26,65.92 | 66.26,61.08 66.67,62.46 | 66.26,61.08 | 66.67,62.46 | 66.67,59.46 67.09,60.84 | 67.09,60.84 | 66.26,61.08 66.67,62.46 | 66.26,61.08 | v66.67,60.96 66.26,61.08 | 67.09,61.08 66.67,62.46 | 66.26,61.08 66.67,62.46 | v66.67,60.96 66.26,61.08 | 67.09,61.08 66.67,62.46 | 67.09,61.08 | v66.67,60.96 67.09,61.08 | 66.26,61.08 66.67,62.46 | v66.67,60.96 66.26,61.08 | 67.09,61.08 66.67,62.46 | v66.67,60.96 67.09,61.08 | 67.09,60.84 66.67,59.46 | 67.09,60.84 v66.67,60.96 | 66.67,59.46 | 66.26,60.84 66.67,59.46 | 66.26,60.84 | 66.26,60.84 v66.67,60.96 | 66.67,59.46 67.09,60.84 | 66.67,59.46 66.26,60.84 | 66.26,60.84 v66.67,60.96 | 67.09,60.84 66.67,59.46 | 67.09,60.84 v66.67,60.96 | 66.67,59.46 66.26,60.84 | v66.67,60.96 66.26,60.84 | 68.7,43.59 70.08,43.18 | 68.7,43.59 | 68.7,43.59 70.08,43.18 | v68.58,43.18 68.7,43.59 | 70.08,43.18 | 68.7,42.77 70.08,43.18 | 68.7,42.77 | v68.58,43.18 68.7,42.77 | 68.7,43.59 70.08,43.18 | 68.7,42.77 70.08,43.18 | v68.58,43.18 68.7,42.77 | 68.7,43.59 70.08,43.18 | v68.58,43.18 68.7,43.59 | 68.7,42.77 70.08,43.18 | v68.58,43.18 68.7,42.77 | 81.16,42.77 79.78,43.18 | 81.16,42.77 | 79.78,43.18 | 79.78,43.18 81.16,42.77 | 81.16,42.77 | v81.28,43.18 81.16,42.77 | 81.16,43.59 79.78,43.18
  Top 0.406: 79.78,43.18 81.16,42.77 | 81.16,42.77 v81.28,43.18 | 79.78,43.18 81.16,43.59 | 81.16,43.59 | 81.16,43.59 v81.28,43.18 | 79.78,43.18 81.16,42.77 | v81.28,43.18 81.16,42.77 | 81.16,43.59 79.78,43.18 | 81.16,43.59 v81.28,43.18 | 66.26,40.13 66.67,41.51 | 66.26,40.13 | 66.67,41.51 | 66.26,40.13 66.67,41.51 | 66.26,40.13 | v66.67,40.01 66.26,40.13 | 67.09,40.13 66.67,41.51 | 66.26,40.13 66.67,41.51 | v66.67,40.01 66.26,40.13 | 67.09,40.13 66.67,41.51 | 67.09,40.13 | v66.67,40.01 67.09,40.13 | 66.26,40.13 66.67,41.51 | v66.67,40.01 66.26,40.13 | 67.09,40.13 66.67,41.51 | v66.67,40.01 67.09,40.13 | 66.16,19.46 67.54,19.05 | 66.16,19.46 | 66.16,19.46 67.54,19.05 | v66.04,19.05 66.16,19.46 | 67.54,19.05 | 66.16,18.64 67.54,19.05 | 66.16,18.64 | v66.04,19.05 66.16,18.64 | 66.16,19.46 67.54,19.05 | 66.16,18.64 67.54,19.05 | v66.04,19.05 66.16,18.64 | 66.16,19.46 67.54,19.05 | v66.04,19.05 66.16,19.46 | 66.16,18.64 67.54,19.05 | v66.04,19.05 66.16,18.64 | 73.53,18.64 72.16,19.05 | 73.53,18.64 73.54,18.64 | 72.16,19.05 | 72.16,19.05 73.54,18.64 | 73.54,18.64 | v73.66,19.05 73.54,18.64 | 73.53,19.46 72.16,19.05 | 72.16,19.05 73.53,18.64 | 73.53,18.64 v73.66,19.05 | 72.16,19.05 73.53,19.46 | 73.53,19.46 73.54,19.46 v73.66,19.05 | 72.16,19.05 73.54,18.64 | v73.66,19.05 73.54,18.64 | 73.53,19.46 72.16,19.05 | 73.53,19.46 v73.66,19.05
  Top 0.61: 72.16,19.05 v73.66,19.05 | 45.95,29.21 | 45.95,29.21 63.27,29.21 | 63.27,29.21 | 66.67,62.46 | 66.67,62.46 66.67,64.54 | 66.67,64.54 | 70.08,43.18 | 70.08,43.18 79.78,43.18 | 79.78,43.18 | 66.67,41.51 | 66.67,41.51 66.67,59.46 | 66.67,59.46 | 67.54,19.05 | 67.54,19.05 72.16,19.05 | 72.16,19.05
  Bottom 0.61: IC6.5 79.38,64.77 78.11,66.04 68.17,66.04 | v66.67,66.04 68.17,66.04 | v66.67,60.96 65.17,60.96 | 65.17,60.96 IC4.9 | v81.28,43.18 81.28,41.68 | 81.28,41.68 IC5.7 | v64.77,29.21 64.77,30.71 | 64.77,30.71 64.77,33.02 66.67,34.92 66.67,38.51 | 66.67,38.51 v66.67,40.01 | v66.67,40.01 67.74,41.07 | 67.74,41.07 68.36,41.7 | 68.36,41.7 68.58,41.91 v68.58,43.18 | v64.77,29.21 64.77,27.71 | 64.77,27.71 IC2.13 64.77,24.77 66.04,23.5 66.04,20.55 | IC3.19 44.45,22.23 44.13,22.54 44.13,24.13 | 44.13,26.67 44.13,24.13 | 44.13,26.67 44.13,27.71 | 44.13,27.71 v44.45,29.21 | 44.13,24.13 R20.2 | 66.04,20.55 v66.04,19.05 | v73.66,19.05 73.66,17.55 | 73.66,17.55 IC7.2 | 64.77,30.71 64.45,29.28 v64.77,29.21 | 64.77,30.71 65.09,29.28 v64.77,29.21 | 64.77,27.71 65.09,29.14 v64.77,29.21 | 64.77,27.71 64.45,29.14 v64.77,29.21 | 44.13,27.71 44.77,29.14 v44.45,29.21 | 44.13,27.71 44.13,29.14 v44.45,29.21 | 68.17,66.04 66.75,66.36 v66.67,66.04 | 68.17,66.04 66.75,65.72 v66.67,66.04 | 65.17,60.96 66.6,60.64 v66.67,60.96 | 65.17,60.96 66.6,61.28 v66.67,60.96 | 68.36,41.7 68.89,43.06 v68.58,43.18 | 68.36,41.7 68.25,43.15 v68.58,43.18 | 81.28,41.68 81.6,43.11 v81.28,43.18 | 81.28,41.68 80.96,43.11 v81.28,43.18 | 66.67,38.51 67,39.93 v66.67,40.01 | 66.67,38.51 66.35,39.93 v66.67,40.01 | 67.74,41.07 66.5,40.28 v66.67,40.01 | 67.74,41.07 66.95,39.83 v66.67,40.01 | 66.04,20.55 65.72,19.12 v66.04,19.05 | 66.04,20.55 66.36,19.12 v66.04,19.05 | 73.66,17.55 73.98,18.98 v73.66,19.05 | 73.66,17.55 73.34,18.98 v73.66,19.05 | JP2.2 40.64,2.22 39.37,0.95 37.15,0.95 36.2,1.91 36.2,4.13 39.37,7.3 39.37,10.48 35.56,14.29 35.56,18.73 39.37,22.54 39.37,25.72 40.32,26.67 44.13,26.67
